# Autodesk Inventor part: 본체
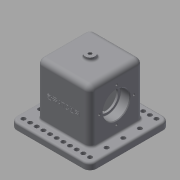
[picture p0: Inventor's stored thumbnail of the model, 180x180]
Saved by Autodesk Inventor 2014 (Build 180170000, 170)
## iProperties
Created: 2018-11
Part Number: 본체
Material: Generic
Document SubType Name: Modeling
Designer: kh
Density: 1 g/cm^3
Appearance: Default
Author: kh
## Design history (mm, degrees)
sketch "스케치1"
  geometry: L1 (-50, -60)-(50, -60); L2 (60, -50)-(60, 50); L3 (50, 60)-(-50, 60); L4 (-60, 50)-(-60, -50); L5 (-60, -60)-(60, 60); L6 (60, -60)-(-60, 60); A1 r 10 centre (-50, 50) between (-50, 60) and (-60, 50); A2 r 10 centre (50, 50) between (60, 50) and (50, 60); A3 r 10 centre (50, -50) between (50, -60) and (60, -50); A4 r 10 centre (-50, -50) between (-60, -50) and (-50, -60); 2 further points
  constraints: 12 end point, 8 point on circle, 8 point on line, 8 tangent, 4 centre point, 3 equal radius, 2 midpoint, 2 parallel, 1 coincident, 1 horizontal, 1 perpendicular
  dimensions: "d0" = 120 distance of L5.end L6.end; "d1" = 120 distance of L6.start L5.end; "d2" = 10 radius of A1
extrude "돌출1" new body sketch "스케치1" distance "d3" = 10; taper "d4" = 0 deg
hole "구멍1" sketch "스케치1" diameter "d5" = 6.6; stored, may be unused: countersink angle "d9" = 90 deg, drill point angle "d11" = 118 deg; dims "d6" = 6, "d7" = 4, "d8" = 2, "d10" = 8
sketch "스케치2"
  geometry: L1 (-40, -40)-(40, -40); L2 (40, -40)-(40, 40); L3 (40, 40)-(-40, 40); L4 (-40, 40)-(-40, -40); L5 (-40, -40)-(40, 40); L6 (40, -40)-(-40, 40); 1 further point
  constraints: 12 end point, 2 midpoint, 2 parallel, 1 horizontal, 1 perpendicular
  dimensions: "d18" = 80 distance of L3.end L2.end; "d19" = 80 distance of L1.end L2.end
extrude "돌출2" join sketch "스케치2" distance "d20" = 80; taper "d21" = 0 deg
sketch "스케치3"
  geometry: L1 (-23, -30)-(23, -30); L2 (23, -30)-(23, 30); L3 (23, 30)-(-23, 30); L4 (-23, 30)-(-23, -30); L5 (-23, -30)-(23, 30); L6 (23, -30)-(-23, 30); 1 further point
  constraints: 12 end point, 2 midpoint, 2 parallel, 1 horizontal, 1 perpendicular
  dimensions: "d22" = 46 distance of L3.end L2.end; "d23" = 60 distance of L1.end L2.end
extrude "돌출3" cut sketch "스케치3" distance "d24" = 80; taper "d25" = 0 deg
node "작업 평면1"
sketch "스케치4"
  geometry: C1 r 7.5 at (0, 0); 1 further point
  constraints: 1 centre point, 1 coincident
  dimensions: "d27" = 15 diameter of C1
extrude "돌출4" join sketch "스케치4" stored distance "d28" = 60; taper "d29" = 0 deg
hole "구멍2" diameter "d32" = 4.917; stored, may be unused: countersink angle "d36" = 90 deg, drill point angle "d38" = 118 deg; dims "d33" = 15, "d34" = 4, "d35" = 2, "d37" = 8, "d39" = 10, "d40" = 10
sketch "스케치5"
  geometry: L1 (23, 0)-(-23, 0) reference; L2 (23, 0)-(23, 80) reference; L3 (23, 80)-(-23, 80) reference; L4 (-23, 0)-(-23, 80) reference; L5 (-40, 10)-(40, 10) reference; L6 (-40, 10)-(-40, 90) reference; L7 (40, 90)-(-40, 90) reference; L8 (40, 10)-(40, 90) reference; L9 (50, 0)-(-50, 0) reference; L10 (-50, 0)-(-50, 10) reference; L11 (50, 10)-(-50, 10) reference; L12 (50, 0)-(50, 10) reference; L13 (40, 48)-(-40, 48); L14 (-40, 48)-(-40, 68); L15 (-26, 68)-(-40, 68); L16 (-26, 68)-(-26, 64.5); L17 (-26, 64.5)-(-23, 64.5); L18 (40, 48)-(40, 68); L19 (40, 68)-(26, 68); L20 (26, 68)-(26, 64.5); L21 (26, 64.5)-(23, 64.5); L22 (23, 64.5)-(23, 48); L23 (-23, 64.5)-(-23, 48); 1 further point
  constraints: 22 end point, 10 point on line, 6 perpendicular, 1 parallel
  dimensions: "d41" = 48 distance between parallel lines of L1 L13; "d42" = 3 distance of L20.end L21.end; "d43" = 3 distance of L16.end L17.end; "d44" = 40 diameter of L15 L13; "d45" = 33 diameter of L17 L13; "d46" = 33 diameter of L21 L13; "d47" = 40 diameter of L19 L13
revolve "회전1" sketch "스케치5" stored, may be unused: angle "d48" = 90 deg
sketch "스케치6"
  geometry: L1 (0, 80)-(0, 0) reference; L2 (0, 80)-(-80, 80) reference; L3 (-80, 0)-(-80, 80) reference; L4 (0, 0)-(-80, 0) reference; L5 (-64, 40)-(-12, 40); L6 (-38, 66)-(-38, 14); C1 r 20 at (-38, 40) reference; A1 r 26 centre (-38, 40) between (-64, 40) and (-12, 40); 5 further points
  constraints: 5 coincident, 4 end point, 4 point on circle, 1 centre point, 1 parallel, 1 perpendicular
  dimensions: "d49" = 52 diameter of A1; "d50" = 52 distance of L5.start L5.end; "d51" = 52 distance of L6.start L6.end
hole "구멍3" sketch "스케치6" at (-64, 40), (-38, 66), (-12, 40), (-38, 14) diameter "d52" = 3.242; stored, may be unused: countersink angle "d56" = 90 deg, drill point angle "d58" = 118 deg; dims "d53" = 8, "d54" = 4, "d55" = 2, "d57" = 10
chamfer "모따기1" distance "d59" = 1; stored, may be unused: second distance "d60" = 2, angle "d61" = 45 deg
fillet "모깎기1" dims "d62" = 3, "d63" = 0.6, "d64" = 8
sketch "스케치7"
  geometry: L1 (-18, -13)-(82, -13) reference; L2 (72, 0)-(72, 69) reference; L3 (6.698, 38.662)-(57.302, 38.662); L4 (57.302, 38.662)-(57.302, 31.338); L5 (57.302, 31.338)-(6.698, 31.338); L6 (6.698, 31.338)-(6.698, 38.662); L7 (6.698, 35)-(57.302, 35); L8 (32, 38.662)-(32, 31.338); 1 further point
  constraints: 4 end point, 4 midpoint, 2 other
  dimensions: "d65" = 40 distance between parallel lines of L2 L8; "d66" = 48 distance between parallel lines of L1 L7
feature "엠보싱1" sketch "스케치7" dims "d67" = 0.5, "d68" = 0
node "솔리드1"
pattern_linear "직사각형 패턴1" dims "d14" = 10
mirror "대칭1"
pattern_linear "직사각형 패턴2" dims "d17" = 25
mirror "대칭2"
mirror "대칭3"
node "투영된 루프1"
node "투영된 루프2"
node "투영된 루프3"
node "투영된 루프4"
other parameters: "d26" = 5
